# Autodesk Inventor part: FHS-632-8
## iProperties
Author: Ron Crain
Shininess: 60.0
PropertySet Name: _Private Model Information
Length Units: 11272
Angle Units: 11286
Time Units: 11279
Mass Units: 11290
Length Display Precision: 5
Angle Display Precision: 2
Compacted: True
Created: 2002-07
Part Number: FHS-632-8
Document SubType Name: Modeling
Designer: Ron Crain
Material: Stainless Steel, Austenitic
Description: STUD, SELF CLINCH,  6-32 UNC X 0.500 in
Vendor: PENN ENG & MFG
Control State: 0
Master: False
Checked Out: False
PropertySet Name: Design Tracking Control
Density: 7.84
Volumn: 0.12502123273002705
Area: 1.8185517691006778
PropertySet Name: Model Information
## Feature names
1. Head [Extrusion]
2. Shank [Extrusion]
3. Chamfer
